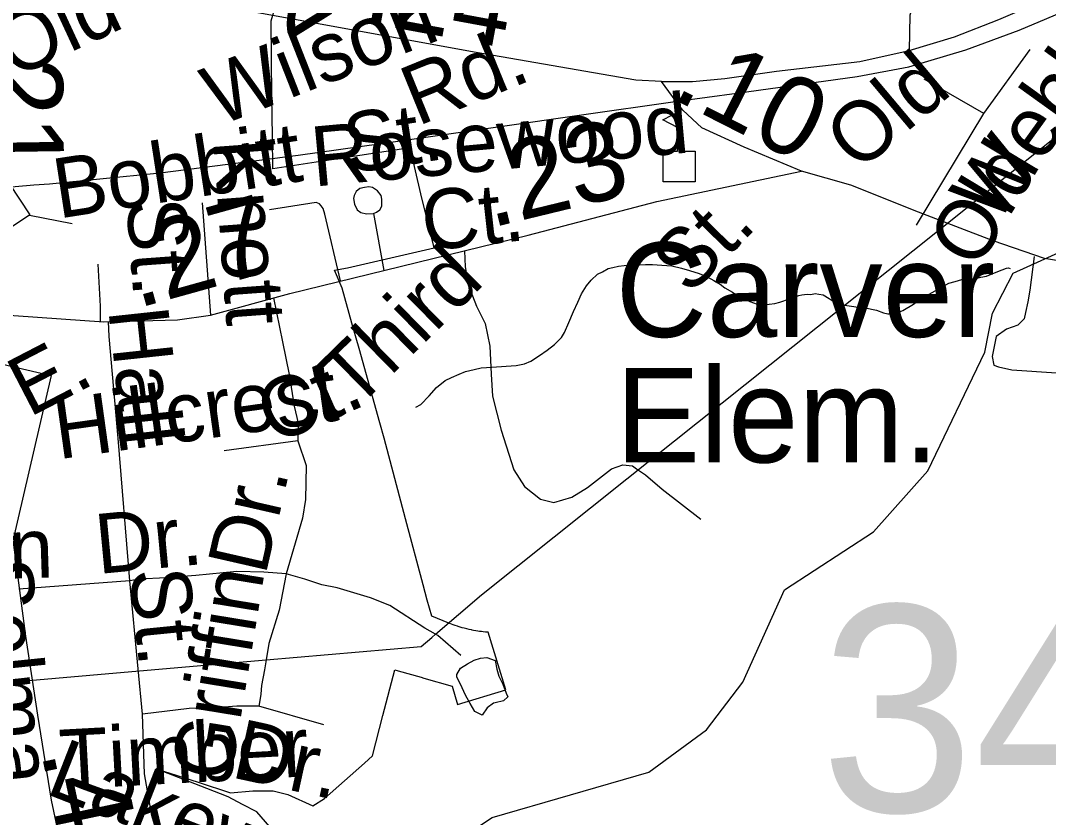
# Model space of a CAD drawing. Extents: x 2001466 to 31450019, y -30647475 to 847247.
# Drawn here: x 2189226 to 2192487, y 738020 to 740550 of the extents above; entities that cross this region are included whole.
import ezdxf

# ---------------------------------------------------------------- set-up
doc = ezdxf.new("R2010")
doc.units = 0
for name, color, linetype in [('Exist Boundary Political City Limit New', 7, 'Continuous'), ('Exist Cultural Educational Facility Elementary CELL', 7, 'Continuous'), ('Exist Cultural Educational Facility Elementary Label', 7, 'Continuous'), ('Exist Hydrographic Creek Single Shore', 7, 'Continuous'), ('Exist Hydrographic Misc Water Feature', 7, 'Continuous'), ('Exist Railroad Mainline', 7, 'Continuous'), ('Exist Road Non-System Type 51', 7, 'Continuous'), ('Exist Road Non-System Type 51 Label', 7, 'Continuous'), ('Exist Road Primary NC Attributed', 7, 'Continuous'), ('Exist Road Primary NC Label', 7, 'Continuous'), ('Exist Road Primary NC Service Mileage Hundredths English Label', 7, 'Continuous'), ('Exist Road Primary NC Shield CELL', 7, 'Continuous'), ('Exist Road Primary NC Structure Standard Bridge CELL', 7, 'Continuous'), ('Exist Road Secondary Mileage Hundredths English Label', 7, 'Continuous'), ('Exist Road Secondary Structure Standard Bridge Number Label', 7, 'Continuous'), ('Exist Road Secondary Type 41 Attributed', 7, 'Continuous'), ('Exist Road Secondary Type 51 Attributed', 7, 'Continuous'), ('Exist Road Secondary Type 51 Label', 7, 'Continuous'), ('Exist Road Secondary Type 51 Number Label', 7, 'Continuous'), ('Exist Utilities Electrical Transmission Line', 7, 'Continuous'), ('Map Preparation Boundary City Limit Buffer Line', 7, 'Continuous')]:
    doc.layers.add(name, color=color, linetype=linetype)

msp = doc.modelspace()

# ---------------------------------------------------------------- linework, layer by layer
at = {"layer": 'Exist Boundary Political City Limit New'}
msp.add_lwpolyline([(2190050.8, 737951.1), (2189975.8, 738037.6), (2189930.2, 738061.6), (2189885, 738085.1), (2189816.8, 738112), (2189656.8, 738174.8), (2189789.5, 738131.7), (2189892, 738098), (2189962.5, 738104.2), (2190027.8, 738104.5), (2190073.8, 738093.3), (2190153, 738056.6), (2190190.5, 738080), (2190317, 738192.7), (2190343.2, 738215.8), (2190375.5, 738343.6), (2190413.5, 738488.7), (2190423.8, 738485.6), (2190497, 738465.2), (2190506, 738462.8), (2190595.8, 738436.7), (2190612.2, 738378.8), (2190765.5, 738425.2), (2190710.2, 738608), (2190706.8, 738608.2), (2190700.8, 738608.8), (2190693.8, 738609.4), (2190688.2, 738610.1), (2190682.2, 738610.8), (2190676.5, 738611.7), (2190670.5, 738612.6), (2190663.5, 738613.9), (2190658.5, 738614.8), (2190656.8, 738615.2), (2190649.2, 738616.8), (2190642, 738618.4), (2190633.8, 738620.6), (2190627.5, 738622.2), (2190620.8, 738624.2), (2190614, 738626.4), (2190612.2, 738626.9), (2190604.8, 738629.5), (2190598.5, 738631.7), (2190593.5, 738633.6), (2190587.8, 738635.8), (2190584.5, 738637.1), (2190530.8, 738659.2), (2190516, 738710.2), (2190503, 738758.6), (2190447.2, 738967.8), (2190379.2, 739224.3), (2190366, 739273.1), (2190327, 739413.9), (2190302.5, 739501), (2190277.5, 739589.6), (2190246.5, 739700.2), (2190221.8, 739757.2), (2190263.2, 739765.4), (2190538.2, 739828.8), (2190496.5, 740000), (2190461.8, 740145.4), (2190191.2, 740104.6), (2190026, 740079.1), (2190025, 740182.9), (2190023.5, 740308.5), (2190020.8, 740549.2), (2190035, 740595.6)], dxfattribs=at)
at = {"layer": 'Exist Cultural Educational Facility Elementary CELL'}
msp.add_lwpolyline([(2191264.9, 740037.9), (2191264.9, 740135.8), (2191310.9, 740135.8), (2191310.9, 740210.9), (2191263.9, 740235.1), (2191320.5, 740264.3), (2191320.5, 740135.8), (2191366.5, 740135.8), (2191366.5, 740037.9)], close=True, dxfattribs=at)
at = {"layer": 'Exist Hydrographic Creek Single Shore'}
msp.add_lwpolyline([(2190188.8, 737942.6), (2190380.9, 737843.6), (2190505.8, 737877.1), (2190721.9, 738020.3), (2191219.8, 738164.2), (2191402.9, 738298.3), (2191517.9, 738450.1), (2191649.8, 738742.6), (2191931.9, 738927.1), (2192104.8, 739120.4), (2192285.8, 739497.2), (2192309.8, 739621.3), (2192375.9, 739747.9), (2192541.8, 739823.3), (2192823.9, 739899.5), (2193131.9, 740021.1), (2193313.8, 740253.6), (2193446.8, 740280.4), (2193450.6, 740280.5)], dxfattribs=at)
at = {"layer": 'Exist Hydrographic Misc Water Feature'}
for points in [[(2190480.2, 739322.5), (2190495.9, 739330.7), (2190522, 739358.8), (2190545.4, 739384.9), (2190573.7, 739406.9), (2190593.1, 739417), (2190617.5, 739427.1), (2190637.4, 739435.4), (2190665.3, 739441.8), (2190687.3, 739447.9), (2190721.1, 739450), (2190767, 739452.4), (2190798.8, 739454.5), (2190824.9, 739460.7), (2190844.9, 739469), (2190872.6, 739487.1), (2190897, 739503.3), (2190920.4, 739521.3), (2190942.3, 739543.6), (2190952.2, 739559.5), (2190966.1, 739591.9), (2190979.9, 739625.9), (2190993.8, 739655.8), (2191005.3, 739682.1), (2191021.3, 739708.1), (2191036.9, 739726), (2191057, 739744.5), (2191072.8, 739752.2), (2191090.6, 739762.5), (2191105, 739766.4), (2191123, 739770.6), (2191158.9, 739774.9), (2191176.9, 739775), (2191208.7, 739775.5), (2191230.9, 739775.4), (2191260.8, 739773.7), (2191292.8, 739771.7), (2191322.9, 739764.3), (2191348.8, 739756.4), (2191379.1, 739746.5), (2191404.9, 739736.5), (2191425.2, 739724.9), (2191445.3, 739713), (2191461.1, 739701.2), (2191485.3, 739687.5), (2191503.2, 739675.4), (2191521.4, 739667.4), (2191539.5, 739657.8), (2191551.4, 739653.5), (2191563.4, 739649.7), (2191585.8, 739647.9), (2191601.4, 739650), (2191619.6, 739652.1), (2191635.6, 739656.2), (2191665.4, 739666.3), (2191695.1, 739676.8), (2191705.1, 739678.9), (2191721.3, 739681), (2191733.2, 739680.8), (2191747.2, 739683.1), (2191759.1, 739680.9), (2191772.8, 739679.3), (2191791.3, 739667.2), (2191807.1, 739657.5), (2191819.4, 739651.6), (2191833.5, 739647.8), (2191883.1, 739639.9), (2191905.5, 739638.2), (2191941.6, 739630.3), (2191963.5, 739622.5), (2191977.9, 739618.7), (2191985.4, 739618.8), (2191997.3, 739619), (2192009.4, 739622.9), (2192025.4, 739629), (2192059.5, 739649.4), (2192080.8, 739665.6), (2192109.1, 739681.7), (2192144.6, 739701.8), (2192170.8, 739716.1), (2192190.9, 739722), (2192212.8, 739728.4), (2192256.5, 739730.7), (2192272.5, 739734.8), (2192290.6, 739739), (2192326.7, 739753), (2192354.1, 739763.4), (2192360.5, 739765.3), (2192366.4, 739763.2)], [(2190726.6, 738382.4), (2190706.3, 738368.4), (2190691, 738344.4), (2190667, 738356.1), (2190652.4, 738381.8), (2190638, 738407.9), (2190622.1, 738443.6), (2190610.4, 738465.6), (2190610, 738473.8), (2190621.8, 738493.5), (2190643.8, 738508), (2190665.7, 738519.7), (2190685.4, 738526.1), (2190705.3, 738528.3), (2190731.8, 738518.2), (2190737.7, 738490.6), (2190743.9, 738468.6), (2190756.2, 738442.8), (2190766.4, 738414.9), (2190772.4, 738402.6), (2190758.4, 738390.5), (2190732.4, 738384.3), (2190726.6, 738382.4)]]:
    msp.add_lwpolyline(points, dxfattribs=at)
at = {"layer": 'Exist Railroad Mainline'}
for points in [[(2191280.3, 740289.5), (2191310.5, 740293.8), (2191499, 740319.9), (2191880, 740372.1), (2192044.6, 740402.7), (2192225.7, 740457), (2192394.9, 740519.5), (2192570.4, 740593.9)], [(2189115.1, 740017.9), (2189161.3, 740019.3), (2189268.3, 740028.9), (2189318.2, 740031.8), (2189477.9, 740047.9), (2189668.5, 740067), (2190107.3, 740122.5), (2190430.8, 740168.6), (2191027.8, 740253.6), (2191280.3, 740289.5)]]:
    msp.add_lwpolyline(points, dxfattribs=at)
at = {"layer": 'Exist Road Non-System Type 51'}
for p, q in [((2192282.5, 740254.4), (2192429, 740458.2)), ((2192282.5, 740254.4), (2192092.6, 740364.3)), ((2192068.4, 739900.2), (2192282.5, 740254.4)), ((2189802.2, 739970.8), (2189828.3, 739614.7)), ((2190345.4, 739937.7), (2190378.5, 739756.7)), ((2190105.7, 739215.9), (2189871.6, 739184.2)), ((2189573, 738771.3), (2189220.9, 738745.2)), ((2189599.1, 738491.9), (2189573, 738771.3)), ((2190542.5, 738601.7), (2190525.2, 738611.3)), ((2189613, 738348.5), (2189599.1, 738491.9)), ((2190188.8, 738314.6), (2189981.9, 738373.3))]:
    msp.add_line(p, q, dxfattribs=at)
for points in [[(2192214.5, 741171.4), (2192179, 741005.8), (2192158.8, 740900.3), (2192120.3, 740777.1), (2192109, 740715.3), (2192073.6, 740644.1), (2192048, 740566.6), (2192045, 740455.4)], [(2190345.4, 739937.7), (2190355.5, 739941.4), (2190365.6, 739949.2), (2190371.9, 739961.1), (2190372.1, 739971.1), (2190372.3, 739983.1), (2190370.6, 739995.1), (2190358.9, 740009.4), (2190343.1, 740019.7), (2190331.1, 740021.9), (2190317.1, 740020.2), (2190303, 740016.5), (2190290.8, 740006.8), (2190284.6, 739994.9), (2190282.4, 739984.9), (2190286, 739966.9), (2190293.6, 739948.7), (2190305.5, 739940.5), (2190323.4, 739936.1), (2190345.4, 739937.7)], [(2190241.5, 739723.3), (2190191.7, 739935.6), (2190186, 739953.7), (2190180.2, 739961.9), (2190174.3, 739968), (2190164.4, 739972.2), (2190016, 739949.2)], [(2190635, 739819.2), (2190636.2, 739768.4), (2190646.8, 739709.1), (2190672.2, 739643.4), (2190699.8, 739588.3), (2190714.6, 739516.2), (2190718.9, 739427.2), (2190723.1, 739357.2), (2190750.6, 739249.1), (2190790.9, 739124), (2190824.8, 739071.1), (2190875.7, 739030.8), (2190918, 739020.2), (2190975, 739037.1), (2191024.4, 739067.6), (2191100.5, 739126.6), (2191136.7, 739139.9), (2191167.1, 739136.1), (2191180.8, 739127.2)], [(2192442.4, 739801.4), (2192428.7, 739693.7), (2192421.5, 739657.4), (2192414.2, 739622.8), (2192410.6, 739602.9), (2192390.6, 739582.9), (2192354.3, 739570.2), (2192321.6, 739546.5), (2192308.9, 739483), (2192314.4, 739455.7), (2192328.9, 739450.3), (2192371.4, 739440.8), (2192513.3, 739431.7), (2192604.8, 739424.8)], [(2189471.4, 739776.2), (2189478.7, 739643.4), (2189478.7, 739594.8)], [(2190028.1, 739669.7), (2190056.7, 739529.6), (2190078.7, 739426), (2190094.4, 739325.5), (2190106.9, 739272.1), (2190105.7, 739215.9)], [(2189573, 738771.3), (2189535.9, 739223.8), (2189507.6, 739547.2), (2189504.8, 739594.4)], [(2190105.7, 739215.9), (2190132.7, 739137.3), (2190130.3, 739029.2), (2190120.5, 738970.3), (2190068.9, 738793.4)], [(2191180.8, 739127.2), (2191209, 739107.6), (2191261.3, 739062.6), (2191384, 738966.7)], [(2190068.9, 738793.4), (2189997.7, 738798.3), (2189911.8, 738800.7), (2189781.7, 738788.5), (2189688.4, 738781.1), (2189602.5, 738776.2), (2189573, 738771.3)], [(2190068.9, 738793.4), (2190046.8, 738677.9), (2190013.4, 738572.7), (2190004.8, 738520.1)], [(2190525.2, 738611.3), (2190508.3, 738620.5), (2190397.9, 738692.7), (2190336.5, 738717.2), (2190230.9, 738749.2), (2190181.8, 738759), (2190127.8, 738776.2), (2190068.9, 738793.4)], [(2190622.5, 738534.2), (2190549.8, 738597.7), (2190542.5, 738601.7)], [(2190004.8, 738520.1), (2189999.7, 738489), (2189990.7, 738439.2), (2189988.1, 738411.3), (2189985, 738391.8), (2189981.9, 738373.3)], [(2189981.9, 738373.3), (2189912.5, 738373.3), (2189846.1, 738368.6), (2189761.2, 738365.5), (2189613, 738348.5)], [(2190395.7, 737377.2), (2190392.4, 737413.4), (2190380, 737461.2), (2190353.8, 737496.8), (2190315.2, 737544.7), (2190236.5, 737628.4), (2190207.2, 737667), (2190184, 737704.1), (2190162.4, 737727.2), (2190117.6, 737752), (2190065.1, 737770.5), (2189987.9, 737798.3), (2189927.7, 737816.8), (2189852.1, 737843.1), (2189784.2, 737864.7), (2189742.5, 737880.2), (2189705.6, 737905.5), (2189682.4, 737931.8), (2189659.3, 737968.8), (2189642.3, 738026), (2189619.2, 738158.9), (2189613, 738348.5)]]:
    msp.add_lwpolyline(points, dxfattribs=at)
at = {"layer": 'Exist Road Primary NC Attributed'}
msp.add_lwpolyline([(2189143.4, 739618.1), (2189167.5, 739324.9), (2189194.7, 738950), (2189241.8, 738596.1), (2189279.4, 738344.8), (2189323.4, 738074.6), (2189406.1, 737685.1), (2189458.4, 737515.4), (2189517, 737347.9), (2189562.5, 737240)], dxfattribs=at)
at = {"layer": 'Exist Road Primary NC Shield CELL'}
msp.add_lwpolyline([(2188192.1, 738719.1), (2188405.3, 739636.5), (2189322.7, 739423.3), (2189109.5, 738505.9)], close=True, dxfattribs=at)
at = {"layer": 'Exist Road Primary NC Structure Standard Bridge CELL'}
msp.add_line((2189254.6, 739932.5), (2189389.9, 739905.2), dxfattribs=at)
msp.add_lwpolyline([(2189088, 740184.6), (2189255.2, 739932.8), (2189137.6, 739854.7), (2188970.4, 740106.5)], close=True, dxfattribs=at)
at = {"layer": 'Exist Road Secondary Type 41 Attributed'}
msp.add_lwpolyline([(2191259.5, 740356.3), (2191357.8, 740356.8), (2191460.4, 740365.7), (2191624.1, 740389.1), (2191889.1, 740420.3), (2192045, 740455.4), (2192189.2, 740498.3), (2192329.6, 740552.9), (2192648.2, 740690.4), (2192800.2, 740764.5), (2193014.6, 740893.2), (2193213.3, 741053.1), (2193303, 741138.9), (2193450.6, 741286.6), (2193458.9, 741294.9), (2193579.7, 741458.7), (2193688.9, 741595.2), (2193794.1, 741716.1), (2193925.6, 741875)], dxfattribs=at)
at = {"layer": 'Exist Road Secondary Type 51 Attributed'}
for points in [[(2191259.5, 740356.3), (2191177.9, 740360.5), (2190671.4, 740448.4), (2189944.2, 740580.4), (2189603, 740634.8), (2189258.8, 740674.2), (2189247.2, 740684.5), (2189239.4, 740694.8), (2189229.1, 740729.6)], [(2191306.5, 740293.2), (2191259.5, 740356.3)], [(2191703.7, 740071.5), (2191522.1, 740147.9), (2191387.1, 740209.7), (2191327.5, 740265.2), (2191306.5, 740293.2)], [(2189143.4, 739618.1), (2189490, 739594), (2189724.4, 739600.3), (2189829.1, 739614.9), (2190080.2, 739684), (2190836.7, 739868.3), (2191244.8, 739975.1), (2191703.7, 740071.5)], [(2194511.1, 739618.1), (2194279.9, 739609.7), (2193950.8, 739609.7), (2193808.5, 739622.2), (2193699.6, 739645.3), (2193581.4, 739684), (2193499.8, 739706), (2193307.8, 739722.8), (2192997, 739752.1), (2192609.3, 739772), (2192474.3, 739795), (2192312.1, 739850.5), (2192075.1, 739941.6), (2191860.6, 740027.5), (2191703.7, 740071.5)]]:
    msp.add_lwpolyline(points, dxfattribs=at)
at = {"layer": 'Exist Utilities Electrical Transmission Line'}
for p, q in [((2191149.5, 739094.8), (2192130.3, 739877.6)), ((2190530.7, 738591.5), (2190542.5, 738601.7)), ((2189554.6, 738481), (2190004.8, 738520.1)), ((2189227.5, 738452.6), (2189554.6, 738481)), ((2188726.4, 738409.1), (2189227.5, 738452.6))]:
    msp.add_line(p, q, dxfattribs=at)
for points in [[(2192130.3, 739877.6), (2192784.4, 740399.5), (2192812.9, 740424.9), (2192855.3, 740446.1), (2193450.6, 740736.2)], [(2190542.5, 738601.7), (2190688.5, 738726.8), (2191149.5, 739094.8)], [(2190004.8, 738520.1), (2190497.1, 738562.8), (2190530.7, 738591.5)]]:
    msp.add_lwpolyline(points, dxfattribs=at)
at = {"layer": 'Map Preparation Boundary City Limit Buffer Line'}
msp.add_lwpolyline([(2190050.8, 737951.1), (2189975.8, 738037.6), (2189930.2, 738061.6), (2189885, 738085.1), (2189816.8, 738112), (2189656.8, 738174.8), (2189789.5, 738131.7), (2189892, 738098), (2189962.5, 738104.2), (2190027.8, 738104.5), (2190073.8, 738093.3), (2190153, 738056.6), (2190190.5, 738080), (2190317, 738192.7), (2190343.2, 738215.8), (2190375.5, 738343.6), (2190413.5, 738488.7), (2190423.8, 738485.6), (2190497, 738465.2), (2190506, 738462.8), (2190595.8, 738436.7), (2190612.2, 738378.8), (2190765.5, 738425.2), (2190710.2, 738608), (2190706.8, 738608.2), (2190700.8, 738608.8), (2190693.8, 738609.4), (2190688.2, 738610.1), (2190682.2, 738610.8), (2190676.5, 738611.7), (2190670.5, 738612.6), (2190663.5, 738613.9), (2190658.5, 738614.8), (2190656.8, 738615.2), (2190649.2, 738616.8), (2190642, 738618.4), (2190633.8, 738620.6), (2190627.5, 738622.2), (2190620.8, 738624.2), (2190614, 738626.4), (2190612.2, 738626.9), (2190604.8, 738629.5), (2190598.5, 738631.7), (2190593.5, 738633.6), (2190587.8, 738635.8), (2190584.5, 738637.1), (2190530.8, 738659.2), (2190516, 738710.2), (2190503, 738758.6), (2190447.2, 738967.8), (2190379.2, 739224.3), (2190366, 739273.1), (2190327, 739413.9), (2190302.5, 739501), (2190277.5, 739589.6), (2190246.5, 739700.2), (2190221.8, 739757.2), (2190263.2, 739765.4), (2190538.2, 739828.8), (2190496.5, 740000), (2190461.8, 740145.4), (2190191.2, 740104.6), (2190026, 740079.1), (2190025, 740182.9), (2190023.5, 740308.5), (2190020.8, 740549.2), (2190035, 740595.6)], dxfattribs=at)

# ---------------------------------------------------------------- texts
at = {"layer": 'Exist Cultural Educational Facility Elementary Label'}
for s, p in [('Carver', (2191114.3, 739545.5)), ('Elem.', (2191114.3, 739147))]:
    msp.add_text(s, height=300, dxfattribs=at).set_placement(p)
at = {"layer": 'Exist Road Non-System Type 51 Label'}
for s, rotation, p in [('Webb', 54.2897, (2192321, 739898.2)), ('Rosewood', 5.1955, (2190156.5, 740022.7)), ('Bobbitt  St.', 8.7885, (2189346.1, 739921)), ('Knott', 274.1844, (2189837, 740169.5)), ('Old', 58.8551, (2192259.4, 739753.6)), ('Ct.', 6.2892, (2190508.4, 739817.7)), ('St.', 274.1844, (2189561.7, 739980.3)), ('Hall', 276.1679, (2189504.4, 739630.9)), ('Hillcrest', 7.9235, (2189345.7, 739156.9)), ('Ct.', 23.5053, (2190029.4, 739202.2)), ('Dr.', 77.1157, (2190003, 738785.6)), ('Dr.', 5.442, (2189472.1, 738792.8)), ('Lawson', 1.7568, (2188456.9, 738755.5)), ('St.', 275.6842, (2189571.9, 738804.3)), ('Griffin', 80.6954, (2189890.8, 738128.7)), ('Timber', 3.0823, (2189354.3, 738108.6)), ('Dr.', 347.6767, (2189890.1, 738148.4)), ('Lakewood', 338.6697, (2189300.8, 738097.2))]:
    msp.add_text(s, height=190, rotation=rotation, dxfattribs=at).set_placement(p)
at = {"layer": 'Exist Road Primary NC Label'}
msp.add_text('Selma', height=190, rotation=275.8804, dxfattribs=at).set_placement((2189070.4, 738832.8))
at = {"layer": 'Exist Road Primary NC Service Mileage Hundredths English Label'}
for s, rotation, p in [('.21', 270.8429, (2189107.7, 740524.2)), ('.46', 281.9813, (2189291, 738227.2))]:
    msp.add_text(s, height=250, rotation=rotation, dxfattribs=at).set_placement(p)
at = {"layer": 'Exist Road Secondary Mileage Hundredths English Label'}
for s, rotation, p in [('.24', 349.564, (2190306.8, 740546.6)), ('.10', 333.0027, (2191286.3, 740305.8)), ('.23', 13.6576, (2190717.8, 739891.5)), ('.27', 15.5671, (2189595.8, 739635.9))]:
    msp.add_text(s, height=250, rotation=rotation, dxfattribs=at).set_placement(p)
at = {"layer": 'Exist Road Secondary Structure Standard Bridge Number Label'}
msp.add_text('34', height=656.17, dxfattribs=at).set_placement((2191763.7, 738037.8))
at = {"layer": 'Exist Road Secondary Type 51 Label'}
for s, rotation, p in [('Old', 24.8466, (2189202.2, 740364.1)), ('Wilson', 21.4131, (2189853.7, 740213.1)), ('Rd.', 22.1645, (2190485.7, 740213.7)), ('Old', 40.0526, (2191883.7, 740065.5)), (' St.', 45.5756, (2191298.9, 739623.3)), ('Third', 44.4335, (2190288.8, 739310.8)), ('E. ', 27.4046, (2189253.3, 739288.9))]:
    msp.add_text(s, height=190, rotation=rotation, dxfattribs=at).set_placement(p)
at = {"layer": 'Exist Road Secondary Type 51 Number Label'}
msp.add_text('2353', height=250, rotation=31.918, dxfattribs=at).set_placement((2190070.9, 740482.3))

doc.saveas('drawing.dxf')
